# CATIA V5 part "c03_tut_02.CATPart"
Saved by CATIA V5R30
Part number: c03tut2
Bounding box of the stored display mesh (mm): x 0 to 0, y -39.994 to 149.998, z -40 to 39.984
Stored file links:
  D:\PROJECTS\CATIA V56R 2020\Resources\c03_catia_v5_6r2020_tut\c03_tut_02.CATPart
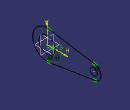
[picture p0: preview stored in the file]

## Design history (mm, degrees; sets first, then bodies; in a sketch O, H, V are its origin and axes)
Body1 (main body)
  Sketch1 on yz-plane, origin (0, 0, 0), H (0, 1, 0), V (0, 0, 1)
    arc A1 centre (0, 0) radius 40 from (6.1538, 39.5238) to (6.1538, -39.5238) ccw
    point P1 (0, -40)
    arc A2 centre (130, 0) radius 20 from (133.0769, -19.7619) to (133.0769, 19.7619) ccw
    point P2 (130, 0)
    line L1 (6.1538, 39.5238) -> (133.0769, 19.7619)
    line L2 (6.1538, -39.5238) -> (133.0769, -19.7619)
    circle A3 centre (0, 0) radius 22.5
    circle A4 centre (130, 0) radius 10
    radius A3 = 22.5
    coincidence: A1 P1, P1 V, P2 H
    tangency: L1 A1, L1 A2, L2 A1, L2 A2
